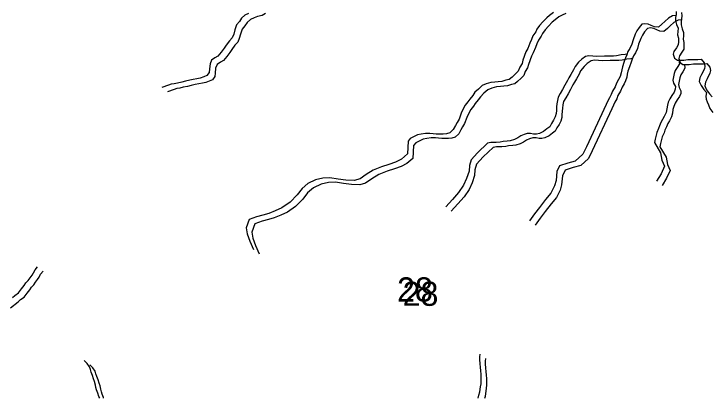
# Model space of a CAD drawing. Extents: x -21.1 to 50.3, y 0 to 22.1.
# Drawn here: x 46.007 to 47.215, y 14.846 to 15.512 of the extents above; entities that cross this region are included whole.
import ezdxf

# ---------------------------------------------------------------- set-up
doc = ezdxf.new("R2010")
doc.units = 0
doc.layers.add('GM_X_Minor_River', color=7, linetype='Continuous')
doc.layers.add('GM_X_Section_Text', color=7, linetype='Continuous')

msp = doc.modelspace()

# ---------------------------------------------------------------- linework, layer by layer
at = {"layer": 'GM_X_Minor_River'}
for points in [[(46.4145, 15.5124), (46.4081, 15.5097), (46.4024, 15.5044), (46.3986, 15.499), (46.3937, 15.4929), (46.3907, 15.4842), (46.3889, 15.4766), (46.3862, 15.4705), (46.3813, 15.4655), (46.3756, 15.4575), (46.3722, 15.4525), (46.3669, 15.4457), (46.3613, 15.4384), (46.356, 15.4357), (46.3503, 15.4315), (46.3477, 15.4251), (46.3469, 15.4167), (46.3462, 15.4106), (46.3424, 15.4049), (46.3367, 15.4026), (46.3307, 15.4006), (46.325, 15.3991), (46.3185, 15.3983), (46.3124, 15.3971), (46.3052, 15.3952), (46.2987, 15.3933), (46.2915, 15.3921), (46.2854, 15.3909), (46.2805, 15.3901), (46.2755, 15.3882), (46.2641, 15.3843)], [(46.4439, 15.5126), (46.4382, 15.5092), (46.4299, 15.5076), (46.4242, 15.5049), (46.4177, 15.5022), (46.412, 15.4969), (46.4083, 15.4915), (46.4033, 15.4854), (46.4003, 15.4767), (46.3985, 15.4691), (46.3959, 15.463), (46.3909, 15.458), (46.3853, 15.45), (46.3819, 15.445), (46.3766, 15.4382), (46.3709, 15.4309), (46.3656, 15.4282), (46.3599, 15.424), (46.3573, 15.4176), (46.3566, 15.4092), (46.3558, 15.4031), (46.3521, 15.3974), (46.3464, 15.3951), (46.3403, 15.3931), (46.3346, 15.3916), (46.3281, 15.3908), (46.322, 15.3896), (46.3148, 15.3877), (46.3084, 15.3858), (46.3011, 15.3846), (46.2951, 15.3834), (46.2901, 15.3826), (46.2852, 15.3807), (46.2738, 15.3768)], [(46.9436, 15.5142), (46.9368, 15.5092), (46.9319, 15.505), (46.9254, 15.4982), (46.9194, 15.4917), (46.9148, 15.4856), (46.913, 15.4806), (46.9081, 15.4738), (46.9054, 15.4677), (46.9028, 15.4612), (46.899, 15.4521), (46.896, 15.446), (46.8908, 15.4315), (46.8893, 15.4258), (46.8851, 15.4197), (46.8825, 15.4128), (46.878, 15.4079), (46.8719, 15.4021), (46.867, 15.3983), (46.8613, 15.3968), (46.8541, 15.3948), (46.848, 15.394), (46.8419, 15.3936), (46.835, 15.3928), (46.8271, 15.3905), (46.8202, 15.3878), (46.8134, 15.3817), (46.8074, 15.376), (46.8036, 15.3706), (46.7983, 15.3641), (46.7953, 15.3592), (46.7904, 15.3534), (46.7866, 15.3462), (46.7836, 15.3397), (46.7798, 15.3295), (46.7764, 15.3237), (46.7734, 15.3184), (46.7697, 15.3115), (46.7636, 15.3058), (46.7579, 15.3039), (46.7522, 15.3031), (46.7472, 15.3031), (46.7404, 15.3034), (46.7347, 15.3041), (46.7293, 15.3045), (46.7217, 15.3044), (46.7141, 15.3033), (46.708, 15.3021), (46.7008, 15.299), (46.6951, 15.2959), (46.6914, 15.291), (46.6902, 15.269)], [(46.9654, 15.5125), (46.9586, 15.5098), (46.9532, 15.5067), (46.9464, 15.5017), (46.9415, 15.4975), (46.9351, 15.4907), (46.929, 15.4842), (46.9245, 15.4781), (46.9226, 15.4731), (46.9177, 15.4663), (46.9151, 15.4602), (46.9124, 15.4537), (46.9087, 15.4446), (46.9057, 15.4385), (46.9004, 15.424), (46.8989, 15.4183), (46.8948, 15.4122), (46.8921, 15.4053), (46.8876, 15.4004), (46.8815, 15.3946), (46.8766, 15.3908), (46.8709, 15.3893), (46.8637, 15.3873), (46.8576, 15.3865), (46.8515, 15.3861), (46.8447, 15.3853), (46.8367, 15.383), (46.8299, 15.3803), (46.823, 15.3742), (46.817, 15.3684), (46.8132, 15.3631), (46.8079, 15.3566), (46.8049, 15.3517), (46.8, 15.3459), (46.7962, 15.3387), (46.7932, 15.3322), (46.7895, 15.3219), (46.7861, 15.3162), (46.7831, 15.3109), (46.7793, 15.304), (46.7732, 15.2983), (46.7675, 15.2964), (46.7618, 15.2956), (46.7569, 15.2956), (46.75, 15.2959), (46.7443, 15.2966), (46.739, 15.297), (46.7314, 15.2969), (46.7238, 15.2958), (46.7177, 15.2946), (46.7105, 15.2915), (46.7048, 15.2884), (46.701, 15.2835), (46.6999, 15.2614)], [(47.1567, 15.5162), (47.1564, 15.5108), (47.1557, 15.5055), (47.1553, 15.5006), (47.1573, 15.4938), (47.16, 15.4873), (47.1596, 15.4812), (47.1589, 15.4759), (47.1604, 15.4698), (47.1605, 15.4634), (47.1601, 15.4581), (47.1571, 15.4531), (47.1526, 15.447), (47.1515, 15.4421), (47.1538, 15.4352), (47.1587, 15.4315), (47.1698, 15.4315), (47.177, 15.4327), (47.1823, 15.4331), (47.1888, 15.4328), (47.1941, 15.4328), (47.2002, 15.4332), (47.2052, 15.4268), (47.2064, 15.4215), (47.2056, 15.4165), (47.2008, 15.4066), (47.1977, 15.4009), (47.1966, 15.3948), (47.1997, 15.3876), (47.2047, 15.3808), (47.2093, 15.3755), (47.2082, 15.3694), (47.2086, 15.3641), (47.2105, 15.3592), (47.2128, 15.3543), (47.2148, 15.3478), (47.2205, 15.341)], [(47.166, 15.5144), (47.1664, 15.5087), (47.166, 15.5033), (47.1653, 15.498), (47.165, 15.4931), (47.1669, 15.4863), (47.1696, 15.4798), (47.1692, 15.4737), (47.1685, 15.4684), (47.1701, 15.4623), (47.1701, 15.4559), (47.1698, 15.4506), (47.1667, 15.4456), (47.1622, 15.4395), (47.1611, 15.4346), (47.1634, 15.4277), (47.1684, 15.424), (47.1794, 15.424), (47.1866, 15.4252), (47.192, 15.4256), (47.1984, 15.4253), (47.2038, 15.4253), (47.2099, 15.4257), (47.2148, 15.4193), (47.216, 15.414), (47.2153, 15.409), (47.2104, 15.3991), (47.2074, 15.3934), (47.2063, 15.3873), (47.2094, 15.3801), (47.2143, 15.3733), (47.2189, 15.368)], [(47.1562, 15.5094), (47.1503, 15.5085), (47.1431, 15.5043), (47.1367, 15.499), (47.1317, 15.4944), (47.1257, 15.489), (47.1188, 15.4894), (47.1131, 15.4916), (47.1082, 15.4939), (47.1024, 15.495), (47.0971, 15.4942), (47.0922, 15.4885), (47.0884, 15.4827), (47.0854, 15.4766), (47.0817, 15.4667), (47.0798, 15.4595), (47.0764, 15.4519), (47.073, 15.4469), (47.0708, 15.4409), (47.0689, 15.4355), (47.0659, 15.4275), (47.0633, 15.4199), (47.0622, 15.415), (47.061, 15.4096), (47.0592, 15.4036), (47.0565, 15.3982), (47.0532, 15.3921), (47.0505, 15.3857), (47.046, 15.3777), (47.0437, 15.3723), (47.0407, 15.3666), (47.0381, 15.3613), (47.0351, 15.3548), (47.0012, 15.2817)], [(47.1658, 15.5019), (47.16, 15.501), (47.1527, 15.4968), (47.1463, 15.4915), (47.1414, 15.4869), (47.1353, 15.4815), (47.1285, 15.4819), (47.1228, 15.4841), (47.1178, 15.4864), (47.1121, 15.4875), (47.1067, 15.4867), (47.1018, 15.481), (47.0981, 15.4752), (47.095, 15.4691), (47.0913, 15.4592), (47.0894, 15.452), (47.0861, 15.4444), (47.0827, 15.4394), (47.0804, 15.4333), (47.0785, 15.428), (47.0755, 15.42), (47.0729, 15.4124), (47.0718, 15.4075), (47.0707, 15.4021), (47.0688, 15.3961), (47.0662, 15.3907), (47.0628, 15.3846), (47.0602, 15.3782), (47.0556, 15.3702), (47.0534, 15.3648), (47.0504, 15.3591), (47.0477, 15.3538), (47.0447, 15.3473), (47.0108, 15.2742)], [(47.0714, 15.4424), (47.0681, 15.4416), (47.0613, 15.4408), (47.0533, 15.4392), (47.0476, 15.4384), (47.0403, 15.4388), (47.0323, 15.4384), (47.0183, 15.4383), (47.0122, 15.4386), (47.0053, 15.439), (46.9992, 15.4382), (46.9928, 15.4332), (46.9871, 15.4282), (46.9811, 15.4206), (46.9784, 15.4149), (46.9739, 15.4069), (46.9705, 15.4012), (46.9679, 15.3962), (46.9633, 15.3886), (46.9596, 15.381), (46.9554, 15.3741), (46.9517, 15.3676), (46.9506, 15.3615), (46.9498, 15.3562), (46.9491, 15.3505), (46.9487, 15.3444), (46.9484, 15.3395), (46.9469, 15.3334), (46.9439, 15.3277), (46.9401, 15.322), (46.9371, 15.3163), (46.9322, 15.3124), (46.9265, 15.3082), (46.9193, 15.3044), (46.914, 15.3036), (46.909, 15.3036), (46.9041, 15.3043), (46.8983, 15.3047), (46.8926, 15.3027), (46.8869, 15.3004), (46.882, 15.297), (46.8759, 15.2939), (46.8687, 15.2916), (46.8634, 15.2912), (46.8562, 15.2904), (46.8512, 15.2896), (46.8444, 15.2892), (46.8352, 15.2887), (46.8292, 15.2879), (46.812, 15.2713)], [(47.081, 15.4349), (47.0777, 15.4341), (47.0709, 15.4333), (47.0629, 15.4317), (47.0572, 15.4309), (47.05, 15.4313), (47.042, 15.4309), (47.0279, 15.4308), (47.0218, 15.4311), (47.0149, 15.4315), (47.0089, 15.4307), (47.0024, 15.4257), (46.9967, 15.4207), (46.9907, 15.4131), (46.9881, 15.4074), (46.9835, 15.3994), (46.9801, 15.3937), (46.9775, 15.3887), (46.973, 15.3811), (46.9692, 15.3735), (46.9651, 15.3666), (46.9613, 15.3601), (46.9602, 15.354), (46.9595, 15.3487), (46.9587, 15.343), (46.9584, 15.3369), (46.958, 15.332), (46.9565, 15.3259), (46.9535, 15.3202), (46.9498, 15.3145), (46.9467, 15.3088), (46.9418, 15.3049), (46.9361, 15.3007), (46.9289, 15.2969), (46.9236, 15.2961), (46.9186, 15.2961), (46.9137, 15.2968), (46.908, 15.2972), (46.9023, 15.2952), (46.8966, 15.2929), (46.8917, 15.2895), (46.8856, 15.2864), (46.8784, 15.2841), (46.873, 15.2837), (46.8658, 15.2829), (46.8609, 15.2821), (46.854, 15.2817), (46.8449, 15.2812), (46.8388, 15.2804), (46.8217, 15.2638)], [(47.1614, 15.4315), (47.1622, 15.4254), (47.1584, 15.4189), (47.155, 15.414), (47.1532, 15.4083), (47.1521, 15.4029), (47.1509, 15.3968), (47.1521, 15.3919), (47.1552, 15.3862), (47.1548, 15.3813), (47.153, 15.376), (47.1488, 15.3706), (47.1454, 15.3645), (47.1428, 15.3588), (47.1413, 15.3535), (47.1406, 15.3474), (47.1391, 15.3409), (47.1357, 15.3341), (47.1327, 15.3291), (47.13, 15.3238), (47.1274, 15.3181), (47.1259, 15.3131), (47.1229, 15.3063), (47.1199, 15.2949), (47.1188, 15.2892), (47.1295, 15.2708)], [(47.171, 15.424), (47.1718, 15.4179), (47.1681, 15.4114), (47.1647, 15.4065), (47.1628, 15.4008), (47.1617, 15.3954), (47.1606, 15.3893), (47.1618, 15.3844), (47.1648, 15.3787), (47.1645, 15.3738), (47.1626, 15.3685), (47.1584, 15.3631), (47.1551, 15.357), (47.1524, 15.3513), (47.1509, 15.346), (47.1502, 15.3399), (47.1487, 15.3334), (47.1453, 15.3266), (47.1423, 15.3216), (47.1397, 15.3163), (47.137, 15.3106), (47.1356, 15.3056), (47.1325, 15.2988), (47.1296, 15.2874), (47.1285, 15.2817), (47.1391, 15.2633)], [(46.812, 15.2713), (46.8008, 15.2591), (46.7978, 15.2488), (46.7971, 15.239), (46.793, 15.2264), (46.7878, 15.215), (46.7788, 15.2024), (46.7683, 15.1898), (46.7567, 15.1776)], [(47.0012, 15.2817), (46.9948, 15.2688), (46.9816, 15.2565), (46.9684, 15.253), (46.9541, 15.2484), (46.9496, 15.2385), (46.9482, 15.2233), (46.9456, 15.2138), (46.9393, 15.2012), (46.9299, 15.1898), (46.9197, 15.1765), (46.9107, 15.1654), (46.9021, 15.1532)], [(47.0108, 15.2742), (47.0044, 15.2613), (46.9913, 15.249), (46.9781, 15.2455), (46.9637, 15.2409), (46.9592, 15.231), (46.9578, 15.2158), (46.9552, 15.2063), (46.9489, 15.1937), (46.9395, 15.1823), (46.9294, 15.169), (46.9204, 15.1579), (46.9118, 15.1457)], [(47.1295, 15.2708), (47.1318, 15.2583), (47.1365, 15.2481), (47.1305, 15.2348), (47.1226, 15.2218)], [(46.6902, 15.269), (46.6797, 15.2602), (46.6695, 15.2548), (46.6582, 15.2509), (46.6453, 15.2466), (46.631, 15.2409), (46.6186, 15.2332), (46.608, 15.2259), (46.5978, 15.2232), (46.5834, 15.2238), (46.5698, 15.2256), (46.5558, 15.2278), (46.5437, 15.227), (46.5308, 15.2242), (46.5176, 15.2177), (46.5075, 15.2089), (46.4989, 15.1979), (46.4865, 15.1856), (46.4725, 15.1757), (46.4608, 15.1703), (46.4495, 15.166), (46.4393, 15.1629), (46.4284, 15.1598), (46.4155, 15.1556), (46.4103, 15.1411), (46.4123, 15.1305), (46.4169, 15.118), (46.423, 15.1033)], [(46.6999, 15.2614), (46.6893, 15.2527), (46.6791, 15.2473), (46.6678, 15.2434), (46.655, 15.2391), (46.6406, 15.2334), (46.6282, 15.2257), (46.6177, 15.2184), (46.6075, 15.2157), (46.5931, 15.2163), (46.5794, 15.2181), (46.5654, 15.2203), (46.5533, 15.2195), (46.5405, 15.2167), (46.5273, 15.2102), (46.5171, 15.2014), (46.5085, 15.1904), (46.4961, 15.1781), (46.4822, 15.1682), (46.4705, 15.1628), (46.4591, 15.1585), (46.4489, 15.1554), (46.438, 15.1523), (46.4252, 15.1481), (46.42, 15.1336), (46.4219, 15.123), (46.4265, 15.1105), (46.4327, 15.0958)], [(46.8217, 15.2638), (46.8104, 15.2516), (46.8074, 15.2413), (46.8068, 15.2315), (46.8027, 15.2189), (46.7975, 15.2075), (46.7885, 15.1949), (46.7779, 15.1823), (46.7663, 15.1701)], [(47.1391, 15.2633), (47.1415, 15.2508), (47.1461, 15.2406), (47.1401, 15.2273), (47.1323, 15.2143)], [(46.0016, 15.0022), (46.0147, 15.0129), (46.0189, 15.0164), (46.0249, 15.021), (46.0301, 15.0275), (46.035, 15.0336), (46.038, 15.0382), (46.0417, 15.0424), (46.0451, 15.0466), (46.0485, 15.0512), (46.0511, 15.0554), (46.0537, 15.0607), (46.0582, 15.0657)], [(46.0051, 15.0204), (46.0092, 15.0239), (46.0153, 15.0285), (46.0205, 15.035), (46.0254, 15.0411), (46.0283, 15.0457), (46.0321, 15.0499), (46.0355, 15.0541), (46.0388, 15.0587), (46.0414, 15.0629), (46.044, 15.0682), (46.0485, 15.0732)], [(46.8129, 14.8458), (46.8144, 14.8506), (46.8158, 14.8567), (46.8172, 14.865), (46.818, 14.8704), (46.8183, 14.8757), (46.8182, 14.8863), (46.8177, 14.8943), (46.8173, 14.8984), (46.8164, 14.906), (46.816, 14.9117), (46.816, 14.917), (46.8167, 14.9219)], [(46.1562, 14.8458), (46.155, 14.8484), (46.1531, 14.8544), (46.1507, 14.8601), (46.1496, 14.8643), (46.1488, 14.8684), (46.1472, 14.8745), (46.1456, 14.879), (46.144, 14.8847), (46.1417, 14.8908), (46.1401, 14.8953), (46.1386, 14.8998), (46.1347, 14.9055), (46.1294, 14.9111)], [(46.8246, 14.8458), (46.8255, 14.8492), (46.8269, 14.8575), (46.8276, 14.8629), (46.8279, 14.8682), (46.8278, 14.8788), (46.8273, 14.8868), (46.8269, 14.8909), (46.8261, 14.8985), (46.8257, 14.9042), (46.8256, 14.9095), (46.8263, 14.9144)], [(46.1631, 14.8458), (46.1627, 14.8469), (46.1604, 14.8526), (46.1592, 14.8568), (46.1584, 14.8609), (46.1568, 14.867), (46.1553, 14.8715), (46.1537, 14.8772), (46.1513, 14.8833), (46.1498, 14.8878), (46.1482, 14.8923), (46.1444, 14.898), (46.139, 14.9036)]]:
    msp.add_lwpolyline(points, dxfattribs=at)

# ---------------------------------------------------------------- texts
at = {"layer": 'GM_X_Section_Text'}
for p in [(46.6722, 15.0132), (46.6818, 15.0057)]:
    msp.add_text('28', height=0.04186, rotation=0, dxfattribs=at).set_placement(p)

doc.saveas('drawing.dxf')
